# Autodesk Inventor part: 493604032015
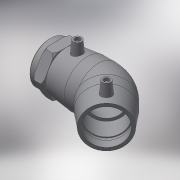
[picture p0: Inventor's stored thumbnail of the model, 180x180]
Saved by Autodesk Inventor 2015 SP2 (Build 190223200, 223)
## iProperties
Created: 2017-06
Part Number: 493604032015
Material: Generic
Description: PLASSON 45° ELBOW TRANSITION FEMALE 32-1.1/2"
Document SubType Name: Modeling
Designer: KIM
Mass: 108.023 g
Surface Area: 379.928 cm^2
Volume: 108.023 cm^3
Density: 1 g/cm^3
Appearance: Default
Author: KIM
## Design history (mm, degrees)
derived "493604.ipt"
feature "Solid1::493604.ipt"
tag "TaggingFeature1"
body "Solid1"
other parameters: "d2" = 44, "d4" = 23.75, "d5" = 39.6, "d8" = 168 deg, "d10" = 15.6, "d11" = 5.2, "d29" = 43, "d30" = 15, "d31" = 33.25, "d34" = 5 deg, "d41" = 4, "d42" = 14, "d43" = 0, "d49" = 32, "d50" = 27.2, "d51" = 15.6, "d52" = 39, "d54" = 135 deg, "d86" = 19.8, "d87" = 135 deg, "d88" = 95, "d90" = 39, "d91" = 0, "d92" = 39, "d93" = 0, "d101" = 3, "d102" = 0, "d107" = 0.1, "d108" = 23, "d110" = 25, "d112" = 52.8, "d113" = 44.845, "d114" = 22.5, "d128" = 15, "d129" = 0, "d132" = 1.6, "d133" = 45 deg, "d134" = 45 deg, "d136" = 0.96, "d_" = 32, "L_1" = 39, "D_" = 23, "A_" = 43, "d_2" = 12, "L_2" = 25, "Rp_" = 44.845, "D_1" = 44
